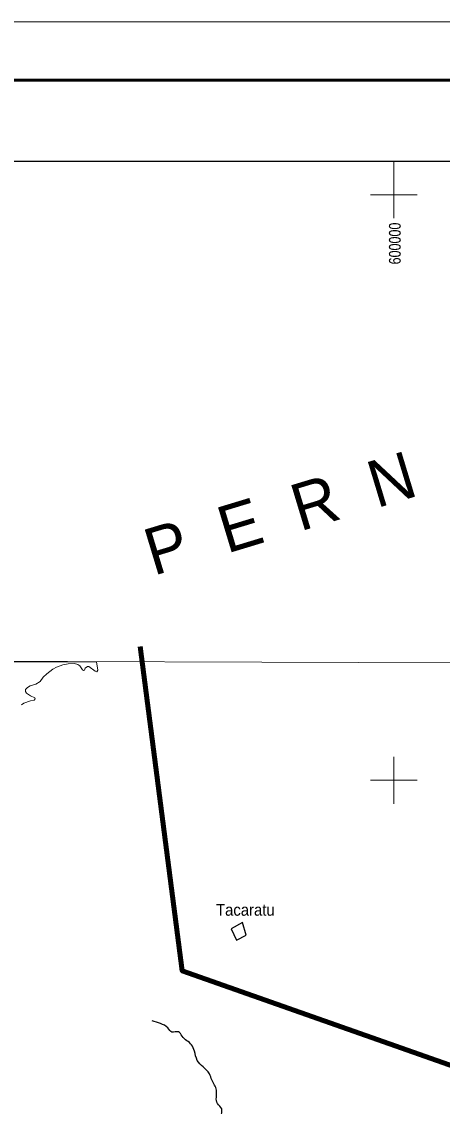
# Model space of a CAD drawing. Extents: x 553962 to 842807, y 8883888 to 9032388.
# Drawn here: x 584103 to 602069, y 8986079 to 9032388 of the extents above; entities that cross this region are included whole.
import ezdxf
from ezdxf.enums import TextEntityAlignment as Align

# ---------------------------------------------------------------- set-up
doc = ezdxf.new("R2010")
doc.units = 0
doc.header["$LTSCALE"] = 20
for name, color, linetype, lineweight in [('1', 7, 'Continuous', 13), ('2', 7, 'Continuous', 13), ('21', 7, 'Continuous', 25), ('24', 7, 'Continuous', 25), ('25', 7, 'Continuous', 13), ('3', 7, 'Continuous', 13), ('9', 7, 'Continuous', 90)]:
    doc.layers.add(name, color=color, linetype=linetype, lineweight=lineweight)
for name, color, linetype in [('41', 7, 'Continuous'), ('42', 7, 'Continuous'), ('47', 7, 'Continuous')]:
    doc.layers.add(name, color=color, linetype=linetype)

msp = doc.modelspace()

# ---------------------------------------------------------------- linework, layer by layer
at = {"layer": '1'}
msp.add_lwpolyline([(565303.24, 9005146.57), (664889.8, 9004806.7), (719872.1, 9004543.9), (790635.75, 9004109.02)], dxfattribs=at)
at = {"layer": '2'}
for p, q in [((600000, 9024000), (600000, 9026438.81)), ((599000, 9025000), (601000, 9025000)), ((600000, 8999000), (600000, 9001000)), ((599000, 9000000), (601000, 9000000))]:
    msp.add_line(p, q, dxfattribs=at)
at = {"layer": '21'}
msp.add_lwpolyline([(593047.14, 8993652.76), (593274.19, 8993173.12), (593688.67, 8993391.54), (593539.99, 8993932.89)], close=True, dxfattribs=at)
at = {"layer": '24'}
msp.add_spline([(593232.05, 8979422.58), (593198.83, 8979610.93), (593054.85, 8979777.11), (592988.4, 8979954.38), (592877.64, 8980164.88), (592722.59, 8980286.75), (592611.84, 8980375.38), (592456.78, 8980729.91), (592146.68, 8981173.07), (591936.25, 8981505.44), (591869.8, 8981682.71), (591814.42, 8981815.66), (591504.31, 8981904.29), (591316.03, 8982048.32), (591216.36, 8982148.03), (591072.38, 8982347.45), (591183.13, 8982491.48), (591526.46, 8982834.93), (591637.22, 8983134.06), (591980.55, 8983211.62), (591958.4, 8983388.88), (591925.17, 8983543.99), (592146.68, 8983832.04), (592445.71, 8983865.28), (592589.69, 8983987.15), (592600.76, 8984208.73), (592777.97, 8984507.86), (592656.14, 8984718.37), (592478.93, 8984851.31), (592456.78, 8985083.97), (592589.69, 8985228), (592633.99, 8985394.19), (592645.06, 8985826.27), (592645.06, 8985970.3), (592467.86, 8986191.88), (592423.54, 8986763.59), (592224.18, 8987206.75), (592124.51, 8987461.57), (591847.62, 8987760.7), (591603.97, 8988037.68), (591482.14, 8988436.53), (591360.31, 8988702.42), (590950.53, 8989079.11), (590806.55, 8989256.37), (590518.59, 8989245.3), (590341.39, 8989422.56), (590031.28, 8989610.9), (589676.88, 8989721.69)], degree=3, dxfattribs=at)
at = {"layer": '25'}
msp.add_line((587296.69, 9005051.95), (574348.14, 9005079.28), dxfattribs=at)
msp.add_lwpolyline([(584099.44, 9003216.88), (584192.44, 9003289.22), (584481.78, 9003391.92), (584629.55, 9003423.69), (584682.66, 9003471.94), (584658.56, 9003520.16), (584473.18, 9003604.02), (584302.8, 9003722.62), (584259.46, 9003783.32), (584268.22, 9003872.06), (584354.69, 9003962.87), (584458.47, 9004027.67), (584711.18, 9004098.94), (584888.43, 9004222.15), (585025.21, 9004408.65), (585173.65, 9004544.09), (585437.57, 9004740.93), (585592.99, 9004822.99), (585860.5, 9004930.9), (586093.95, 9004976.5), (586360.64, 9004989.49), (586505.16, 9004939.95), (586587.33, 9004879.49), (586702.23, 9004719.4), (586749.77, 9004689.18), (586792.55, 9004705.97), (586819.36, 9004784.71), (586914.3, 9004864.1), (586966.08, 9004855.33), (587240.68, 9004654.38), (587315.84, 9004635.1), (587350.58, 9004699.9), (587296.69, 9005051.95)], dxfattribs=at)
msp.add_lwpolyline([(584099.44, 9003216.88), (584192.44, 9003289.22), (584481.78, 9003391.92), (584629.55, 9003423.69), (584682.66, 9003471.94), (584658.56, 9003520.16), (584473.18, 9003604.02), (584302.8, 9003722.62), (584259.46, 9003783.32), (584268.22, 9003872.06), (584354.69, 9003962.87), (584458.47, 9004027.67), (584711.18, 9004098.94), (584888.43, 9004222.15), (585025.21, 9004408.65), (585173.65, 9004544.09), (585437.57, 9004740.93), (585592.99, 9004822.99), (585860.5, 9004930.9), (586093.95, 9004976.5), (586360.64, 9004989.49), (586505.16, 9004939.95), (586587.33, 9004879.49), (586702.23, 9004719.4), (586749.77, 9004689.18), (586792.55, 9004705.97), (586819.36, 9004784.71), (586914.3, 9004864.1), (586966.08, 9004855.33), (587240.68, 9004654.38), (587315.84, 9004635.1), (587350.58, 9004699.9), (587296.69, 9005051.95)], dxfattribs=at)
at = {"layer": '3'}
msp.add_lwpolyline([(842807.26, 9032387.81), (842807.26, 8883887.81), (553961.7, 8883887.81), (553961.7, 9032387.81)], close=True, dxfattribs=at)
at = {"layer": '3', "lineweight": 53}
msp.add_lwpolyline([(840307.26, 9029887.81), (840307.26, 8886387.81), (560211.7, 8886387.81), (560211.7, 9029887.81)], close=True, dxfattribs=at)
at = {"layer": '3', "lineweight": 25}
msp.add_lwpolyline([(563033.89, 9026438.81), (793061.13, 9026438.81), (793495.55, 8889836.82), (563468.3, 8889836.82)], close=True, dxfattribs=at)
at = {"layer": '9'}
msp.add_lwpolyline([(605873.82, 8986618.4), (590956.64, 8991866.66), (589162.97, 9005713.67)], dxfattribs=at)

# ---------------------------------------------------------------- texts
at = {"layer": '41', "width": 0.95}
msp.add_text('Tacaratu', height=500, dxfattribs=at).set_placement((592402.25, 8994216.45))
at = {"layer": '42'}
msp.add_text('P  E  R  N  A  M  B  U  C  O', height=2000, rotation=16.855, dxfattribs=at).set_placement((589730.89, 9008723.54))
at = {"layer": '47', "width": 0.8}
msp.add_text('600000', height=500, rotation=90, dxfattribs=at).set_placement((600290.62, 9022917.37), align=Align.CENTER)

doc.saveas('drawing.dxf')
